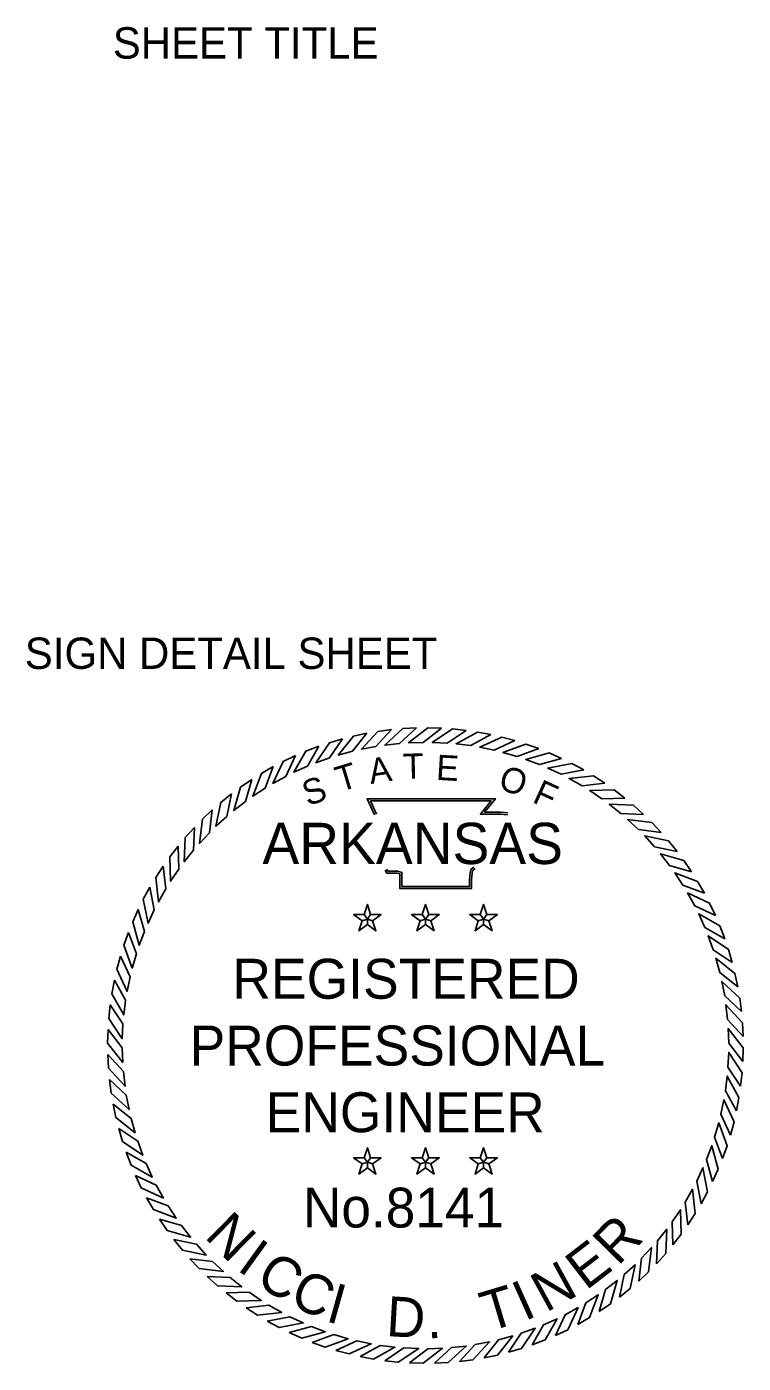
# Model space of a CAD drawing. Extents: x 1001970.7 to 1001981.7, y 1841248.9 to 1841315.4.
import ezdxf

# ---------------------------------------------------------------- set-up
doc = ezdxf.new("R2010")
doc.units = 0
doc.layers.add('G-ANNO-SYMB', color=7, linetype='Continuous')
doc.layers.add('G-ANNO-TEXT', color=7, linetype='Continuous')

msp = doc.modelspace()

# ---------------------------------------------------------------- linework, layer by layer
at = {"layer": 'G-ANNO-SYMB'}
for points in [[(1001977.669, 1841307.285), (1001977.513, 1841307.265), (1001977.323, 1841307.061), (1001977.489, 1841307.093)], [(1001977.955, 1841307.305), (1001977.798, 1841307.297), (1001977.592, 1841307.108), (1001977.76, 1841307.127)], [(1001978.241, 1841307.302), (1001978.084, 1841307.306), (1001977.864, 1841307.134), (1001978.033, 1841307.139)], [(1001978.526, 1841307.276), (1001978.37, 1841307.293), (1001978.137, 1841307.139), (1001978.306, 1841307.131)], [(1001978.809, 1841307.228), (1001978.654, 1841307.257), (1001978.41, 1841307.122), (1001978.578, 1841307.101)], [(1001977.106, 1841307.18), (1001976.956, 1841307.135), (1001976.8, 1841306.904), (1001976.959, 1841306.961)], [(1001977.386, 1841307.244), (1001977.232, 1841307.211), (1001977.058, 1841306.993), (1001977.221, 1841307.037)], [(1001979.086, 1841307.159), (1001978.935, 1841307.199), (1001978.681, 1841307.084), (1001978.847, 1841307.049)], [(1001979.358, 1841307.067), (1001979.21, 1841307.12), (1001978.947, 1841307.024), (1001979.11, 1841306.977)], [(1001976.567, 1841306.987), (1001976.426, 1841306.92), (1001976.307, 1841306.667), (1001976.456, 1841306.748)], [(1001976.833, 1841307.094), (1001976.686, 1841307.038), (1001976.549, 1841306.795), (1001976.703, 1841306.865)], [(1001979.621, 1841306.955), (1001979.478, 1841307.019), (1001979.209, 1841306.944), (1001979.367, 1841306.884)], [(1001976.311, 1841306.86), (1001976.175, 1841306.782), (1001976.077, 1841306.52), (1001976.218, 1841306.613)], [(1001979.875, 1841306.822), (1001979.737, 1841306.897), (1001979.463, 1841306.844), (1001979.616, 1841306.772)], [(1001976.065, 1841306.713), (1001975.935, 1841306.624), (1001975.858, 1841306.356), (1001975.992, 1841306.46)], [(1001980.118, 1841306.67), (1001979.986, 1841306.755), (1001979.708, 1841306.724), (1001979.856, 1841306.64)], [(1001975.831, 1841306.547), (1001975.709, 1841306.449), (1001975.654, 1841306.175), (1001975.779, 1841306.289)], [(1001980.348, 1841306.499), (1001980.223, 1841306.595), (1001979.944, 1841306.585), (1001980.084, 1841306.49)], [(1001975.612, 1841306.363), (1001975.498, 1841306.256), (1001975.464, 1841305.978), (1001975.58, 1841306.102)], [(1001980.563, 1841306.311), (1001980.447, 1841306.416), (1001980.168, 1841306.428), (1001980.3, 1841306.322)], [(1001980.764, 1841306.106), (1001980.656, 1841306.22), (1001980.378, 1841306.254), (1001980.502, 1841306.138)], [(1001975.407, 1841306.163), (1001975.302, 1841306.047), (1001975.29, 1841305.768), (1001975.396, 1841305.9)], [(1001980.947, 1841305.886), (1001980.849, 1841306.008), (1001980.575, 1841306.064), (1001980.689, 1841305.939)], [(1001975.219, 1841305.947), (1001975.123, 1841305.823), (1001975.133, 1841305.544), (1001975.228, 1841305.684)], [(1001981.113, 1841305.653), (1001981.025, 1841305.782), (1001980.756, 1841305.859), (1001980.86, 1841305.725)], [(1001975.048, 1841305.717), (1001974.962, 1841305.586), (1001974.994, 1841305.308), (1001975.078, 1841305.456)], [(1001981.26, 1841305.407), (1001981.182, 1841305.543), (1001980.92, 1841305.641), (1001981.013, 1841305.499)], [(1001974.896, 1841305.475), (1001974.82, 1841305.337), (1001974.874, 1841305.063), (1001974.946, 1841305.216)], [(1001977.392, 1841305.111), (1001977.429, 1841305.163), (1001977.392, 1841305.278), (1001977.354, 1841305.163)], [(1001978.059, 1841305.111), (1001978.096, 1841305.163), (1001978.059, 1841305.278), (1001978.021, 1841305.163)], [(1001978.726, 1841305.111), (1001978.763, 1841305.163), (1001978.726, 1841305.278), (1001978.688, 1841305.163)], [(1001981.387, 1841305.15), (1001981.32, 1841305.292), (1001981.067, 1841305.41), (1001981.149, 1841305.262)], [(1001974.763, 1841305.221), (1001974.699, 1841305.078), (1001974.773, 1841304.809), (1001974.833, 1841304.967)], [(1001977.392, 1841305.111), (1001977.354, 1841305.163), (1001977.233, 1841305.163), (1001977.331, 1841305.091)], [(1001977.392, 1841305.111), (1001977.331, 1841305.091), (1001977.294, 1841304.976), (1001977.392, 1841305.047)], [(1001977.392, 1841305.111), (1001977.452, 1841305.091), (1001977.55, 1841305.163), (1001977.429, 1841305.163)], [(1001977.392, 1841305.111), (1001977.392, 1841305.047), (1001977.49, 1841304.976), (1001977.452, 1841305.091)], [(1001978.059, 1841305.111), (1001978.021, 1841305.163), (1001977.9, 1841305.163), (1001977.998, 1841305.091)], [(1001978.059, 1841305.111), (1001977.998, 1841305.091), (1001977.961, 1841304.976), (1001978.059, 1841305.047)], [(1001978.059, 1841305.111), (1001978.119, 1841305.091), (1001978.217, 1841305.163), (1001978.096, 1841305.163)], [(1001978.059, 1841305.111), (1001978.059, 1841305.047), (1001978.157, 1841304.976), (1001978.119, 1841305.091)], [(1001978.726, 1841305.111), (1001978.688, 1841305.163), (1001978.567, 1841305.163), (1001978.665, 1841305.091)], [(1001978.726, 1841305.111), (1001978.665, 1841305.091), (1001978.628, 1841304.976), (1001978.726, 1841305.047)], [(1001978.726, 1841305.111), (1001978.786, 1841305.091), (1001978.884, 1841305.163), (1001978.763, 1841305.163)], [(1001978.726, 1841305.111), (1001978.726, 1841305.047), (1001978.824, 1841304.976), (1001978.786, 1841305.091)], [(1001981.494, 1841304.885), (1001981.438, 1841305.031), (1001981.195, 1841305.169), (1001981.265, 1841305.014)], [(1001974.65, 1841304.958), (1001974.598, 1841304.81), (1001974.693, 1841304.547), (1001974.741, 1841304.71)], [(1001981.58, 1841304.611), (1001981.536, 1841304.762), (1001981.304, 1841304.918), (1001981.361, 1841304.759)], [(1001974.559, 1841304.686), (1001974.518, 1841304.535), (1001974.634, 1841304.28), (1001974.668, 1841304.446)], [(1001981.644, 1841304.332), (1001981.611, 1841304.486), (1001981.393, 1841304.66), (1001981.437, 1841304.496)], [(1001974.489, 1841304.409), (1001974.46, 1841304.254), (1001974.596, 1841304.01), (1001974.617, 1841304.178)], [(1001981.685, 1841304.049), (1001981.665, 1841304.204), (1001981.461, 1841304.395), (1001981.493, 1841304.228)], [(1001974.441, 1841304.126), (1001974.425, 1841303.97), (1001974.579, 1841303.737), (1001974.587, 1841303.906)], [(1001981.705, 1841303.763), (1001981.697, 1841303.92), (1001981.508, 1841304.126), (1001981.527, 1841303.957)], [(1001974.416, 1841303.841), (1001974.411, 1841303.684), (1001974.584, 1841303.464), (1001974.578, 1841303.633)], [(1001981.702, 1841303.477), (1001981.706, 1841303.633), (1001981.534, 1841303.854), (1001981.54, 1841303.684)], [(1001981.676, 1841303.191), (1001981.693, 1841303.347), (1001981.539, 1841303.58), (1001981.531, 1841303.411)], [(1001974.413, 1841303.554), (1001974.421, 1841303.398), (1001974.61, 1841303.192), (1001974.591, 1841303.36)], [(1001974.432, 1841303.269), (1001974.452, 1841303.113), (1001974.657, 1841302.923), (1001974.625, 1841303.089)], [(1001981.628, 1841302.909), (1001981.657, 1841303.063), (1001981.522, 1841303.308), (1001981.501, 1841303.139)], [(1001974.474, 1841302.985), (1001974.506, 1841302.832), (1001974.725, 1841302.658), (1001974.68, 1841302.821)], [(1001981.559, 1841302.631), (1001981.6, 1841302.783), (1001981.484, 1841303.037), (1001981.449, 1841302.871)], [(1001974.538, 1841302.706), (1001974.582, 1841302.556), (1001974.814, 1841302.399), (1001974.756, 1841302.559)], [(1001981.467, 1841302.36), (1001981.52, 1841302.508), (1001981.424, 1841302.77), (1001981.377, 1841302.607)], [(1001981.355, 1841302.096), (1001981.419, 1841302.239), (1001981.344, 1841302.509), (1001981.284, 1841302.35)], [(1001974.624, 1841302.433), (1001974.679, 1841302.286), (1001974.923, 1841302.149), (1001974.853, 1841302.303)], [(1001977.392, 1841302.318), (1001977.354, 1841302.37), (1001977.233, 1841302.37), (1001977.331, 1841302.299)], [(1001977.392, 1841302.318), (1001977.429, 1841302.37), (1001977.392, 1841302.485), (1001977.354, 1841302.37)], [(1001977.392, 1841302.318), (1001977.452, 1841302.299), (1001977.55, 1841302.37), (1001977.429, 1841302.37)], [(1001978.059, 1841302.318), (1001978.021, 1841302.37), (1001977.9, 1841302.37), (1001977.998, 1841302.299)], [(1001978.059, 1841302.318), (1001978.096, 1841302.37), (1001978.059, 1841302.485), (1001978.021, 1841302.37)], [(1001978.059, 1841302.318), (1001978.119, 1841302.299), (1001978.217, 1841302.37), (1001978.096, 1841302.37)], [(1001978.726, 1841302.318), (1001978.688, 1841302.37), (1001978.567, 1841302.37), (1001978.665, 1841302.299)], [(1001978.726, 1841302.318), (1001978.763, 1841302.37), (1001978.726, 1841302.485), (1001978.688, 1841302.37)], [(1001978.726, 1841302.318), (1001978.786, 1841302.299), (1001978.884, 1841302.37), (1001978.763, 1841302.37)], [(1001977.392, 1841302.318), (1001977.331, 1841302.299), (1001977.294, 1841302.183), (1001977.392, 1841302.255)], [(1001977.392, 1841302.318), (1001977.392, 1841302.255), (1001977.49, 1841302.183), (1001977.452, 1841302.299)], [(1001978.059, 1841302.318), (1001977.998, 1841302.299), (1001977.961, 1841302.183), (1001978.059, 1841302.255)], [(1001978.059, 1841302.318), (1001978.059, 1841302.255), (1001978.157, 1841302.183), (1001978.119, 1841302.299)], [(1001978.726, 1841302.318), (1001978.665, 1841302.299), (1001978.628, 1841302.183), (1001978.726, 1841302.255)], [(1001978.726, 1841302.318), (1001978.726, 1841302.255), (1001978.824, 1841302.183), (1001978.786, 1841302.299)], [(1001981.222, 1841301.843), (1001981.297, 1841301.98), (1001981.244, 1841302.255), (1001981.172, 1841302.101)], [(1001974.73, 1841302.167), (1001974.797, 1841302.025), (1001975.051, 1841301.907), (1001974.969, 1841302.056)], [(1001974.858, 1841301.911), (1001974.936, 1841301.775), (1001975.198, 1841301.677), (1001975.104, 1841301.818)], [(1001981.07, 1841301.6), (1001981.156, 1841301.731), (1001981.124, 1841302.009), (1001981.04, 1841301.862)], [(1001980.899, 1841301.37), (1001980.995, 1841301.494), (1001980.985, 1841301.774), (1001980.89, 1841301.634)], [(1001975.005, 1841301.665), (1001975.093, 1841301.535), (1001975.362, 1841301.458), (1001975.258, 1841301.592)], [(1001975.17, 1841301.431), (1001975.269, 1841301.309), (1001975.543, 1841301.253), (1001975.429, 1841301.379)], [(1001980.711, 1841301.154), (1001980.816, 1841301.271), (1001980.828, 1841301.55), (1001980.722, 1841301.418)], [(1001980.506, 1841300.954), (1001980.62, 1841301.062), (1001980.654, 1841301.339), (1001980.538, 1841301.216)], [(1001975.354, 1841301.212), (1001975.462, 1841301.098), (1001975.739, 1841301.063), (1001975.616, 1841301.179)], [(1001980.286, 1841300.77), (1001980.408, 1841300.869), (1001980.464, 1841301.143), (1001980.339, 1841301.029)], [(1001975.554, 1841301.007), (1001975.671, 1841300.902), (1001975.95, 1841300.889), (1001975.818, 1841300.995)], [(1001975.77, 1841300.819), (1001975.894, 1841300.723), (1001976.174, 1841300.733), (1001976.034, 1841300.828)], [(1001980.053, 1841300.604), (1001980.182, 1841300.693), (1001980.259, 1841300.962), (1001980.125, 1841300.858)], [(1001976, 1841300.648), (1001976.131, 1841300.562), (1001976.409, 1841300.594), (1001976.262, 1841300.678)], [(1001979.807, 1841300.457), (1001979.943, 1841300.536), (1001980.041, 1841300.797), (1001979.899, 1841300.704)], [(1001976.243, 1841300.496), (1001976.38, 1841300.42), (1001976.655, 1841300.474), (1001976.501, 1841300.546)], [(1001979.285, 1841300.223), (1001979.431, 1841300.279), (1001979.569, 1841300.523), (1001979.414, 1841300.453)], [(1001979.55, 1841300.33), (1001979.692, 1841300.397), (1001979.81, 1841300.651), (1001979.662, 1841300.569)], [(1001976.496, 1841300.363), (1001976.64, 1841300.299), (1001976.909, 1841300.373), (1001976.751, 1841300.433)], [(1001979.011, 1841300.138), (1001979.162, 1841300.182), (1001979.318, 1841300.414), (1001979.159, 1841300.356)], [(1001976.76, 1841300.25), (1001976.908, 1841300.198), (1001977.17, 1841300.293), (1001977.008, 1841300.34)], [(1001977.031, 1841300.159), (1001977.183, 1841300.118), (1001977.437, 1841300.234), (1001977.271, 1841300.268)], [(1001977.309, 1841300.089), (1001977.463, 1841300.06), (1001977.708, 1841300.196), (1001977.54, 1841300.217)], [(1001978.163, 1841300.013), (1001978.32, 1841300.021), (1001978.526, 1841300.209), (1001978.357, 1841300.191)], [(1001978.449, 1841300.032), (1001978.604, 1841300.052), (1001978.795, 1841300.257), (1001978.629, 1841300.225)], [(1001978.732, 1841300.074), (1001978.886, 1841300.106), (1001979.06, 1841300.325), (1001978.896, 1841300.28)], [(1001977.591, 1841300.041), (1001977.747, 1841300.025), (1001977.981, 1841300.179), (1001977.811, 1841300.187)], [(1001977.877, 1841300.016), (1001978.034, 1841300.011), (1001978.254, 1841300.183), (1001978.084, 1841300.178)]]:
    msp.add_lwpolyline(points, close=True, dxfattribs=at)
for points in [[(1001977.475, 1841306.306), (1001977.389, 1841306.49), (1001978.861, 1841306.491), (1001978.738, 1841306.337), (1001978.838, 1841306.338), (1001978.921, 1841306.339), (1001979.005, 1841306.33)], [(1001977.496, 1841306.316), (1001977.426, 1841306.467), (1001978.812, 1841306.468), (1001978.689, 1841306.313), (1001978.838, 1841306.315), (1001978.92, 1841306.316), (1001979.002, 1841306.307)], [(1001978.629, 1841305.69), (1001978.604, 1841305.669), (1001978.595, 1841305.639), (1001978.587, 1841305.562), (1001978.587, 1841305.461), (1001977.766, 1841305.461), (1001977.766, 1841305.598), (1001977.766, 1841305.628), (1001977.733, 1841305.639), (1001977.616, 1841305.639), (1001977.595, 1841305.67)], [(1001978.614, 1841305.708), (1001978.583, 1841305.682), (1001978.572, 1841305.643), (1001978.564, 1841305.564), (1001978.564, 1841305.484), (1001977.789, 1841305.484), (1001977.789, 1841305.598), (1001977.789, 1841305.646), (1001977.736, 1841305.662), (1001977.628, 1841305.662), (1001977.614, 1841305.683)]]:
    msp.add_lwpolyline(points, dxfattribs=at)

# ---------------------------------------------------------------- texts
for s, height, rotation, p in [('A', 0.29, 8.6788, (1001977.43, 1841306.66)), ('T', 0.29, 1.4789, (1001977.804, 1841306.718)), ('E', 0.29, 356.672, (1001978.176, 1841306.709)), ('T', 0.29, 16.9015, (1001977.077, 1841306.568)), ('O', 0.29, 341.2218, (1001978.88, 1841306.61)), ('S', 0.29, 19.7726, (1001976.708, 1841306.403)), ('F', 0.29, 335.3628, (1001979.272, 1841306.457)), ('N', 0.459, 315.2676, (1001975.511, 1841301.459)), ('R', 0.459, 45.478, (1001980.268, 1841301.119)), ('I', 0.459, 324.2141, (1001975.884, 1841301.089)), ('E', 0.459, 37.6498, (1001979.901, 1841300.841)), ('C', 0.459, 328.6873, (1001976.091, 1841300.928)), ('N', 0.459, 28.7033, (1001979.441, 1841300.589)), ('C', 0.459, 336.5155, (1001976.481, 1841300.685)), ('I', 0.459, 344.3437, (1001976.901, 1841300.498)), ('T', 0.459, 16.7747, (1001978.777, 1841300.37)), ('I', 0.459, 24.2301, (1001979.197, 1841300.491)), ('D', 0.459, 356.6451, (1001977.601, 1841300.324)), ('.', 0.459, 4.846, (1001978.081, 1841300.292))]:
    msp.add_text(s, height=height, rotation=rotation, dxfattribs=at).set_placement(p)
for s, height, p in [('ARKANSAS', 0.4737, (1001976.187, 1841305.742)), ('REGISTERED', 0.4585, (1001975.843, 1841304.196)), ('PROFESSIONAL', 0.45855, (1001975.351, 1841303.429)), ('ENGINEER', 0.4585, (1001976.225, 1841302.663)), ('No.8141', 0.4567, (1001976.652, 1841301.57))]:
    msp.add_text(s, height=height, dxfattribs=at).set_placement(p)
at = {"layer": 'G-ANNO-TEXT'}
for s, p in [('SHEET TITLE', (1001974.47, 1841314.988)), ('SIGN DETAIL SHEET', (1001973.46, 1841307.982))]:
    msp.add_text(s, height=0.36, dxfattribs=at).set_placement(p)

doc.saveas('drawing.dxf')
